// Mitsubishi GX Works2 project: 模拟量输入输出案例   PLC: FX3U/FX3UC

PROGRAM MAIN
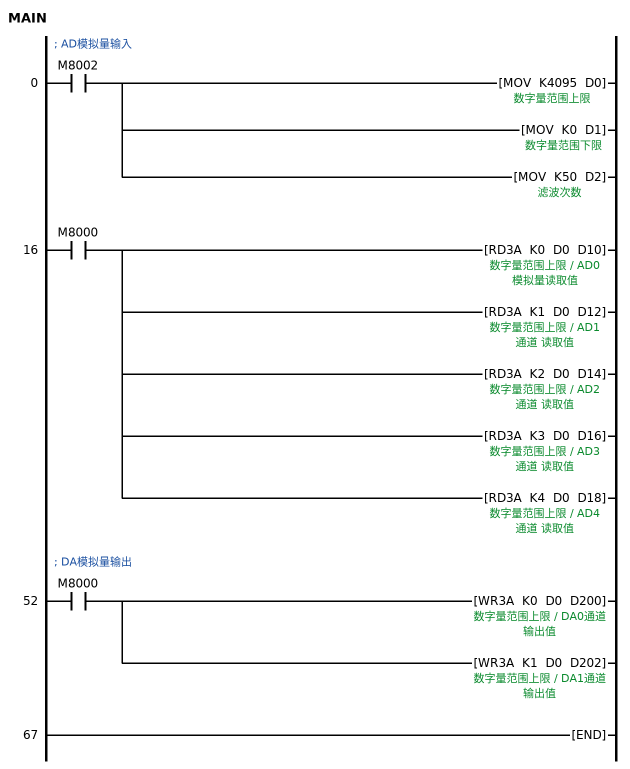
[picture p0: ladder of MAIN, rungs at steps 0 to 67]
; AD模拟量输入
0     LD      M8002
      MOV     K4095 D0  ; 数字量范围上限
        [note] 固定数字量范围4095~0
      MOV     K0 D1  ; 数字量范围下限
      MOV     K50 D2  ; 滤波次数
        [note] 滤波范围0~128 默认50
16    LD      M8000
      RD3A    K0 D0 D10  ; AD0 模拟量读取值
        [note] RD3A 通道地址 读取范围 读取地址
      RD3A    K1 D0 D12  ; AD1 通道 读取值
      RD3A    K2 D0 D14  ; AD2 通道 读取值
      RD3A    K3 D0 D16  ; AD3 通道 读取值
      RD3A    K4 D0 D18  ; AD4 通道 读取值
; DA模拟量输出
52    LD      M8000
      WR3A    K0 D0 D200  ; DA0通道   输出值
        [note] WR3A 通道地址 输出范围 输出数值
      WR3A    K1 D0 D202  ; DA1通道   输出值
67    END
END_PROGRAM

// device comments not shown above
D100  ; 模拟量输出上量程
D101  ; 模拟量输出下量程
D500  ; 输入模拟量上量程
D502  ; 输入模拟量下量程
D504  ; 滤波次数0-28
